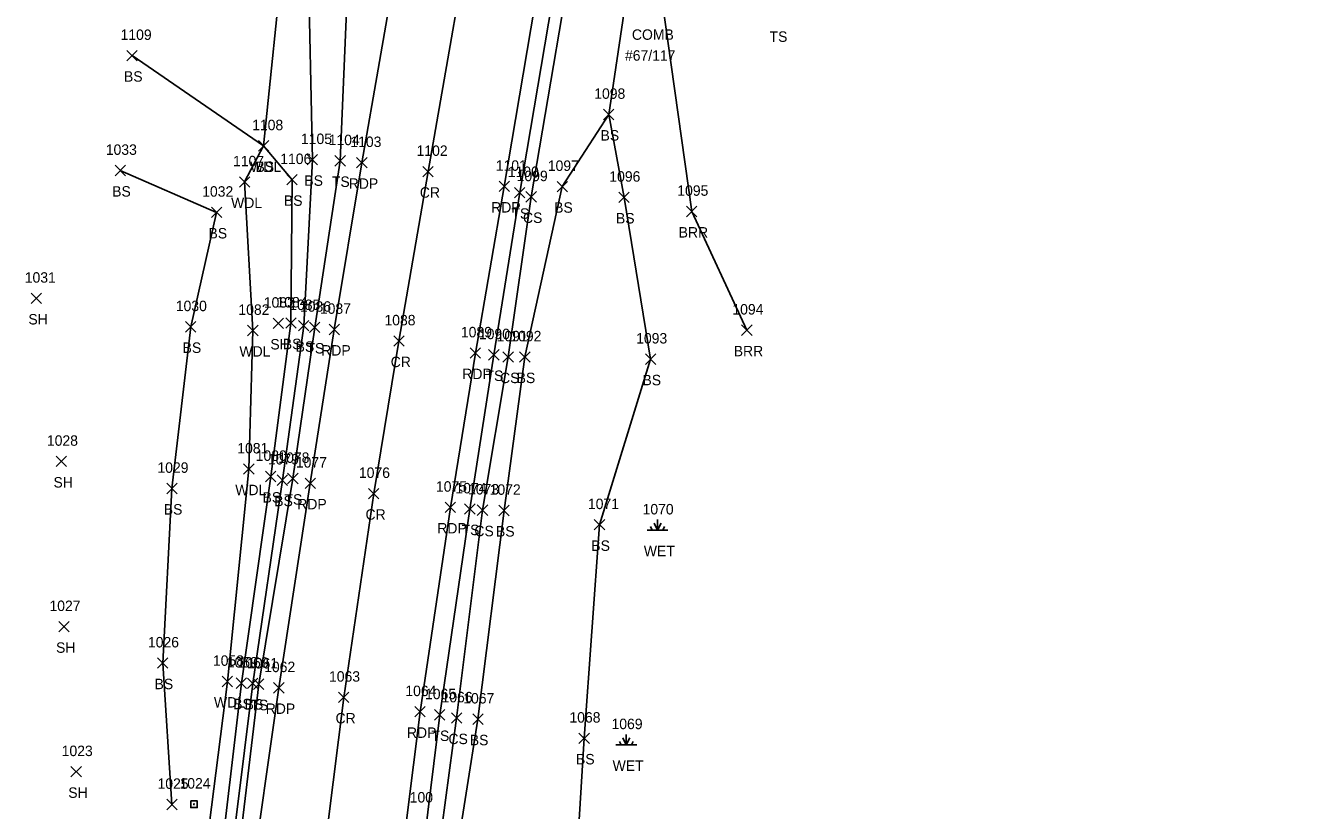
# Model space of a CAD drawing. Extents: x 1654425 to 1656893, y 667839 to 678429.
# Drawn here: x 1654466.9 to 1654714.2, y 667954.2 to 668104.4 of the extents above; entities that cross this region are included whole.
import ezdxf

# ---------------------------------------------------------------- set-up
doc = ezdxf.new("R2010")
doc.units = 0
for name, color, linetype in [('C_I', 7, 'Continuous'), ('L_A', 7, 'Continuous'), ('L_I', 7, 'Continuous'), ('L_TIC', 7, 'Continuous'), ('LABL', 7, 'Continuous'), ('LAWA', 7, 'Continuous'), ('LELB', 7, 'Continuous'), ('LWET', 7, 'Continuous'), ('P_A', 7, 'Continuous'), ('P_I', 7, 'Continuous'), ('P_TIC', 7, 'Continuous'), ('PET', 7, 'Continuous'), ('PRC', 7, 'Continuous'), ('S_I', 7, 'Continuous'), ('SRM', 7, 'Continuous'), ('U_A', 7, 'Continuous'), ('U_C', 7, 'Continuous')]:
    doc.layers.add(name, color=color, linetype=linetype)

msp = doc.modelspace()

# ---------------------------------------------------------------- linework, layer by layer
at = {"layer": 'L_TIC'}
for points in [[(1654486.26, 668097.75), (1654488.26, 668099.75)], [(1654488.26, 668097.75), (1654486.26, 668099.75)], [(1654577.54, 668086.47), (1654579.54, 668088.47)], [(1654579.54, 668086.47), (1654577.54, 668088.47)], [(1654577.54, 668086.47), (1654579.54, 668088.47)], [(1654579.54, 668086.47), (1654577.54, 668088.47)], [(1654511.45, 668080.46), (1654513.45, 668082.46)], [(1654513.45, 668080.46), (1654511.45, 668082.46)], [(1654511.45, 668080.46), (1654513.45, 668082.46)], [(1654513.45, 668080.46), (1654511.45, 668082.46)], [(1654520.8, 668077.81), (1654522.8, 668079.81)], [(1654522.8, 668077.81), (1654520.8, 668079.81)], [(1654526.11, 668077.6), (1654528.11, 668079.6)], [(1654528.11, 668077.6), (1654526.11, 668079.6)], [(1654484, 668075.74), (1654486, 668077.74)], [(1654486, 668075.74), (1654484, 668077.74)], [(1654507.8, 668073.55), (1654509.8, 668075.55)], [(1654509.8, 668073.55), (1654507.8, 668075.55)], [(1654516.89, 668073.98), (1654518.89, 668075.98)], [(1654518.89, 668073.98), (1654516.89, 668075.98)], [(1654568.65, 668072.66), (1654570.65, 668074.66)], [(1654570.65, 668072.66), (1654568.65, 668074.66)], [(1654560.5, 668071.5), (1654562.5, 668073.5)], [(1654562.5, 668071.5), (1654560.5, 668073.5)], [(1654562.69, 668070.7), (1654564.69, 668072.7)], [(1654564.69, 668070.7), (1654562.69, 668072.7)], [(1654580.49, 668070.6), (1654582.49, 668072.6)], [(1654582.49, 668070.6), (1654580.49, 668072.6)], [(1654502.45, 668067.73), (1654504.45, 668069.73)], [(1654504.45, 668067.73), (1654502.45, 668069.73)], [(1654593.45, 668067.9), (1654595.45, 668069.9)], [(1654595.45, 668067.9), (1654593.45, 668069.9)], [(1654467.9, 668051.26), (1654469.9, 668053.26)], [(1654469.9, 668051.26), (1654467.9, 668053.26)], [(1654497.49, 668045.81), (1654499.49, 668047.81)], [(1654499.49, 668045.81), (1654497.49, 668047.81)], [(1654509.39, 668045.1), (1654511.39, 668047.1)], [(1654511.39, 668045.1), (1654509.39, 668047.1)], [(1654514.25, 668046.47), (1654516.25, 668048.47)], [(1654516.25, 668046.47), (1654514.25, 668048.47)], [(1654516.68, 668046.52), (1654518.68, 668048.52)], [(1654518.68, 668046.52), (1654516.68, 668048.52)], [(1654519.13, 668046.02), (1654521.13, 668048.02)], [(1654521.13, 668046.02), (1654519.13, 668048.02)], [(1654521.23, 668045.7), (1654523.23, 668047.7)], [(1654523.23, 668045.7), (1654521.23, 668047.7)], [(1654604, 668045.16), (1654606, 668047.16)], [(1654606, 668045.16), (1654604, 668047.16)], [(1654555.54, 668040.44), (1654557.54, 668042.44)], [(1654557.54, 668040.44), (1654555.54, 668042.44)], [(1654558.28, 668040.03), (1654560.28, 668042.03)], [(1654560.28, 668040.03), (1654558.28, 668042.03)], [(1654561.47, 668040.03), (1654563.47, 668042.03)], [(1654563.47, 668040.03), (1654561.47, 668042.03)], [(1654585.57, 668039.61), (1654587.57, 668041.61)], [(1654587.57, 668039.61), (1654585.57, 668041.61)], [(1654472.72, 668020.03), (1654474.72, 668022.03)], [(1654474.72, 668020.03), (1654472.72, 668022.03)], [(1654508.61, 668018.56), (1654510.61, 668020.56)], [(1654510.61, 668018.56), (1654508.61, 668020.56)], [(1654512.8, 668017.14), (1654514.8, 668019.14)], [(1654514.8, 668017.14), (1654512.8, 668019.14)], [(1654515.04, 668016.45), (1654517.04, 668018.45)], [(1654517.04, 668016.45), (1654515.04, 668018.45)], [(1654517.04, 668016.75), (1654519.04, 668018.75)], [(1654519.04, 668016.75), (1654517.04, 668018.75)], [(1654493.89, 668014.85), (1654495.89, 668016.85)], [(1654495.89, 668014.85), (1654493.89, 668016.85)], [(1654550.95, 668010.91), (1654552.95, 668012.91)], [(1654552.95, 668010.91), (1654550.95, 668012.91)], [(1654553.38, 668010.7), (1654555.38, 668012.7)], [(1654555.38, 668010.7), (1654553.38, 668012.7)], [(1654557.51, 668010.64), (1654559.51, 668012.64)], [(1654559.51, 668010.64), (1654557.51, 668012.64)], [(1654575.77, 668007.9), (1654577.77, 668009.9)], [(1654577.77, 668007.9), (1654575.77, 668009.9)], [(1654473.2, 667988.38), (1654475.2, 667990.38)], [(1654475.2, 667988.38), (1654473.2, 667990.38)], [(1654492.12, 667981.41), (1654494.12, 667983.41)], [(1654494.12, 667981.41), (1654492.12, 667983.41)], [(1654504.51, 667977.89), (1654506.51, 667979.89)], [(1654506.51, 667977.89), (1654504.51, 667979.89)], [(1654507.18, 667977.57), (1654509.18, 667979.57)], [(1654509.18, 667977.57), (1654507.18, 667979.57)], [(1654509.36, 667977.52), (1654511.36, 667979.52)], [(1654511.36, 667977.52), (1654509.36, 667979.52)], [(1654510.52, 667977.38), (1654512.52, 667979.38)], [(1654512.52, 667977.38), (1654510.52, 667979.38)], [(1654545.18, 667971.49), (1654547.18, 667973.49)], [(1654547.18, 667971.49), (1654545.18, 667973.49)], [(1654548.41, 667970.89), (1654550.41, 667972.89)], [(1654550.41, 667970.89), (1654548.41, 667972.89)], [(1654552.5, 667970.67), (1654554.5, 667972.67)], [(1654554.5, 667970.67), (1654552.5, 667972.67)], [(1654572.84, 667967.01), (1654574.84, 667969.01)], [(1654574.84, 667967.01), (1654572.84, 667969.01)], [(1654475.54, 667960.6), (1654477.54, 667962.6)], [(1654477.54, 667960.6), (1654475.54, 667962.6)], [(1654493.9, 667954.33), (1654495.9, 667956.33)], [(1654495.9, 667954.33), (1654493.9, 667956.33)]]:
    msp.add_lwpolyline(points, dxfattribs=at)
at = {"layer": 'LABL'}
msp.add_lwpolyline([(1654605, 668046.16), (1654594.45, 668068.9), (1654587.86, 668115.59), (1654591.34, 668138.45), (1654594.61, 668153.33), (1654611.07, 668168.74), (1654623.05, 668204.29), (1654669.38, 668214.79), (1654714.24, 668210.79)], dxfattribs=at)
at = {"layer": 'LAWA'}
msp.add_lwpolyline([(1654487.86, 667850.24), (1654494.84, 667897.34), (1654500.67, 667940.77), (1654505.51, 667978.89), (1654509.61, 668019.56), (1654510.39, 668046.1), (1654508.8, 668074.55), (1654512.45, 668081.46), (1654516.35, 668119.35), (1654498.68, 668136.06), (1654489.89, 668151.28)], dxfattribs=at)
at = {"layer": 'LELB'}
for points in [[(1654495.43, 667849.08), (1654500.81, 667895.96), (1654505.52, 667939.5), (1654510.36, 667978.52), (1654516.04, 668017.45), (1654520.13, 668047.02), (1654521.8, 668078.81), (1654520.96, 668117.25), (1654511.8, 668137.4), (1654509.93, 668148.4), (1654514.52, 668176.02), (1654523.2, 668207.52), (1654535.05, 668244.08), (1654541.09, 668271.34), (1654546.04, 668295.57), (1654553.44, 668325.52), (1654559.28, 668346.56), (1654565.49, 668358.45)], [(1654497.51, 667848.84), (1654501.99, 667895.85), (1654506.8, 667938.86), (1654511.52, 667978.38), (1654518.04, 668017.75), (1654522.23, 668046.7), (1654527.11, 668078.6), (1654529.66, 668139.05), (1654535.37, 668180.01), (1654543.78, 668219.73), (1654556.62, 668268.25), (1654562.63, 668297.63), (1654565.24, 668311.03), (1654570.38, 668336.59), (1654576.33, 668345.51)], [(1654532.88, 667846.44), (1654536.81, 667893.31), (1654541.08, 667931.05), (1654546.18, 667972.49), (1654551.95, 668011.91), (1654556.54, 668041.44), (1654561.5, 668072.5), (1654571.11, 668129.18), (1654578.93, 668172.43), (1654586.94, 668211.68), (1654595.67, 668254.34), (1654607.41, 668286.92), (1654610.93, 668292.61), (1654617.54, 668318.12), (1654616.79, 668336.32)], [(1654543.76, 667929.96), (1654549.41, 667971.89), (1654554.38, 668011.7), (1654559.28, 668041.03), (1654563.69, 668071.7), (1654573.34, 668128.44), (1654581.87, 668172.56), (1654590.31, 668210.74), (1654599.29, 668252.88), (1654609.98, 668283.91), (1654610.93, 668292.61)], [(1654538.26, 667846.15), (1654542.65, 667893.12), (1654546.8, 667929.18), (1654553.5, 667971.67), (1654558.51, 668011.64), (1654562.47, 668041.03), (1654569.65, 668073.66), (1654578.54, 668087.47), (1654583.04, 668117.51)], [(1654492.62, 667849.25), (1654498.76, 667895.88), (1654503.7, 667940.07), (1654508.18, 667978.57), (1654513.8, 668018.14), (1654517.68, 668047.52), (1654517.89, 668074.98), (1654512.45, 668081.46), (1654487.26, 668098.75)], [(1654570.91, 667920.09), (1654573.84, 667968.01), (1654576.77, 668008.9), (1654586.57, 668040.61), (1654581.49, 668071.6), (1654578.54, 668087.47)], [(1654494.9, 667955.33), (1654493.12, 667982.41), (1654494.89, 668015.85), (1654498.49, 668046.81), (1654503.45, 668068.73), (1654485, 668076.74)]]:
    msp.add_lwpolyline(points, dxfattribs=at)
at = {"layer": 'LWET'}
for p, q in [((1654589.89, 668007.88), (1654585.89, 668007.88)), ((1654586.89, 668007.88), (1654586.56, 668008.55)), ((1654587.89, 668007.88), (1654587.22, 668009.21)), ((1654587.89, 668007.88), (1654587.89, 668009.88)), ((1654587.89, 668007.88), (1654588.56, 668009.21)), ((1654588.89, 668007.88), (1654589.22, 668008.55)), ((1654581.91, 667966.76), (1654581.24, 667968.09)), ((1654581.91, 667966.76), (1654581.91, 667968.76)), ((1654581.91, 667966.76), (1654582.58, 667968.09)), ((1654583.91, 667966.76), (1654579.91, 667966.76)), ((1654580.91, 667966.76), (1654580.58, 667967.42)), ((1654582.91, 667966.76), (1654583.24, 667967.42))]:
    msp.add_line(p, q, dxfattribs=at)
at = {"layer": 'P_TIC'}
for points in [[(1654530.26, 668077.24), (1654532.26, 668079.24)], [(1654532.26, 668077.24), (1654530.26, 668079.24)], [(1654542.94, 668075.54), (1654544.94, 668077.54)], [(1654544.94, 668075.54), (1654542.94, 668077.54)], [(1654557.55, 668072.69), (1654559.55, 668074.69)], [(1654559.55, 668072.69), (1654557.55, 668074.69)], [(1654524.99, 668045.3), (1654526.99, 668047.3)], [(1654526.99, 668045.3), (1654524.99, 668047.3)], [(1654537.36, 668043.09), (1654539.36, 668045.09)], [(1654539.36, 668043.09), (1654537.36, 668045.09)], [(1654552.01, 668040.79), (1654554.01, 668042.79)], [(1654554.01, 668040.79), (1654552.01, 668042.79)], [(1654520.39, 668015.85), (1654522.39, 668017.85)], [(1654522.39, 668015.85), (1654520.39, 668017.85)], [(1654532.53, 668013.87), (1654534.53, 668015.87)], [(1654534.53, 668013.87), (1654532.53, 668015.87)], [(1654547.22, 668011.23), (1654549.22, 668013.23)], [(1654549.22, 668011.23), (1654547.22, 668013.23)], [(1654514.37, 667976.68), (1654516.37, 667978.68)], [(1654516.37, 667976.68), (1654514.37, 667978.68)], [(1654526.79, 667974.85), (1654528.79, 667976.85)], [(1654528.79, 667974.85), (1654526.79, 667976.85)], [(1654541.41, 667972.09), (1654543.41, 667974.09)], [(1654543.41, 667972.09), (1654541.41, 667974.09)]]:
    msp.add_lwpolyline(points, dxfattribs=at)
at = {"layer": 'PET'}
for points in [[(1654500.93, 667848.14), (1654504.78, 667896.02), (1654509.67, 667937.82), (1654515.37, 667977.68), (1654521.39, 668016.85), (1654525.99, 668046.3), (1654531.26, 668078.24), (1654541.38, 668136.51), (1654548.54, 668178.15), (1654556.41, 668219.5), (1654564.06, 668264.06), (1654572.07, 668308.08), (1654579.91, 668345.23), (1654595.42, 668341.51), (1654611.88, 668337.75)], [(1654528.99, 667846.47), (1654531.96, 667893.38), (1654537.26, 667931.97), (1654542.41, 667973.09), (1654548.22, 668012.23), (1654553.01, 668041.79), (1654558.55, 668073.69), (1654568.05, 668129.99), (1654575.97, 668172.91), (1654583.21, 668212.31), (1654592.64, 668255.65), (1654604.22, 668302.74), (1654611.88, 668337.75)]]:
    msp.add_lwpolyline(points, dxfattribs=at)
at = {"layer": 'PRC'}
msp.add_lwpolyline([(1654514.39, 667847.42), (1654517.73, 667895.01), (1654522.68, 667935.26), (1654527.79, 667975.85), (1654533.53, 668014.87), (1654538.36, 668044.09), (1654543.94, 668076.54), (1654553.86, 668133.31), (1654561.61, 668175.74), (1654568.95, 668214.62), (1654577.86, 668259.83), (1654587.68, 668305.21), (1654595.42, 668341.51)], dxfattribs=at)
at = {"layer": 'SRM'}
msp.add_lwpolyline([(1654498.49, 667956), (1654499.74, 667956), (1654499.74, 667954.75), (1654498.49, 667954.75)], close=True, dxfattribs=at)
msp.add_circle((1654499.11, 667955.38), 0.0833, dxfattribs=at)

# ---------------------------------------------------------------- texts
at = {"layer": 'C_I'}
msp.add_text('100', height=2, dxfattribs=at).set_placement((1654540.43, 667955.71))
at = {"layer": 'L_A'}
for s, p in [('TS', (1654609.35, 668101.38)), ('BS', (1654485.7, 668093.75)), ('BS', (1654576.98, 668082.47)), ('BS', (1654576.98, 668082.47)), ('WDL', (1654509.87, 668076.46)), ('BS', (1654510.89, 668076.46)), ('BS', (1654520.25, 668073.81)), ('TS', (1654525.52, 668073.6)), ('BS', (1654483.44, 668071.74)), ('BS', (1654516.33, 668069.98)), ('WDL', (1654506.22, 668069.55)), ('TS', (1654559.91, 668067.5)), ('BS', (1654568.09, 668068.66)), ('CS', (1654562.13, 668066.7)), ('BS', (1654579.93, 668066.6)), ('BS', (1654501.89, 668063.73)), ('BRR', (1654591.94, 668063.9)), ('SH', (1654467.39, 668047.26)), ('BS', (1654496.93, 668041.81)), ('WDL', (1654507.81, 668041.1)), ('SH', (1654513.74, 668042.47)), ('BS', (1654516.12, 668042.52)), ('BS', (1654518.58, 668042.02)), ('TS', (1654520.64, 668041.7)), ('BRR', (1654602.49, 668041.16)), ('TS', (1654554.95, 668036.44)), ('CS', (1654557.73, 668036.03)), ('BS', (1654560.91, 668036.03)), ('BS', (1654585.01, 668035.61)), ('SH', (1654472.2, 668016.03)), ('WDL', (1654507.02, 668014.56)), ('BS', (1654512.24, 668013.14)), ('BS', (1654493.33, 668010.85)), ('BS', (1654514.48, 668012.45)), ('TS', (1654516.45, 668012.75)), ('TS', (1654550.36, 668006.91)), ('CS', (1654552.82, 668006.7)), ('BS', (1654556.95, 668006.64)), ('BS', (1654575.21, 668003.9)), ('WET', (1654585.27, 668002.88)), ('SH', (1654472.69, 667984.38)), ('BS', (1654491.56, 667977.41)), ('WDL', (1654502.93, 667973.89)), ('BS', (1654506.62, 667973.57)), ('BS', (1654508.8, 667973.52)), ('TS', (1654509.93, 667973.38)), ('TS', (1654544.59, 667967.49)), ('CS', (1654547.85, 667966.89)), ('BS', (1654551.94, 667966.67)), ('BS', (1654572.28, 667963.01)), ('WET', (1654579.29, 667961.76)), ('SH', (1654475.03, 667956.6))]:
    msp.add_text(s, height=2, dxfattribs=at).set_placement(p)
at = {"layer": 'L_I'}
for s, p in [('1109', (1654485.05, 668101.75)), ('1098', (1654575.77, 668090.47)), ('1098', (1654575.77, 668090.47)), ('1108', (1654510.25, 668084.46)), ('1108', (1654510.25, 668084.46)), ('1033', (1654482.22, 668079.74)), ('1105', (1654519.6, 668081.81)), ('1104', (1654524.91, 668081.6)), ('1107', (1654506.59, 668077.55)), ('1106', (1654515.63, 668077.98)), ('1100', (1654559.21, 668075.5)), ('1097', (1654566.88, 668076.66)), ('1099', (1654560.91, 668074.7)), ('1096', (1654578.66, 668074.6)), ('1032', (1654500.68, 668071.73)), ('1095', (1654591.68, 668071.9)), ('1031', (1654466.7, 668055.26)), ('1083', (1654512.48, 668050.47)), ('1084', (1654514.91, 668050.52)), ('1085', (1654517.36, 668050.02)), ('1030', (1654495.63, 668049.81)), ('1082', (1654507.62, 668049.1)), ('1086', (1654519.41, 668049.7)), ('1094', (1654602.23, 668049.16)), ('1090', (1654553.68, 668044.44)), ('1091', (1654557.08, 668044.03)), ('1092', (1654559.7, 668044.03)), ('1093', (1654583.8, 668043.61)), ('1028', (1654470.94, 668024.03)), ('1081', (1654507.4, 668022.56)), ('1080', (1654510.94, 668021.14)), ('1079', (1654513.26, 668020.45)), ('1078', (1654515.27, 668020.75)), ('1029', (1654492.11, 668018.85)), ('1074', (1654549.18, 668014.91)), ('1073', (1654551.61, 668014.7)), ('1072', (1654555.74, 668014.64)), ('1071', (1654574.56, 668011.9)), ('1070', (1654585.03, 668010.88)), ('1027', (1654471.43, 667992.38)), ('1026', (1654490.29, 667985.41)), ('1058', (1654502.74, 667981.89)), ('1059', (1654505.4, 667981.57)), ('1060', (1654507.45, 667981.52)), ('1061', (1654509.26, 667981.38)), ('1065', (1654543.36, 667975.49)), ('1066', (1654546.53, 667974.89)), ('1067', (1654550.68, 667974.67)), ('1068', (1654571.02, 667971.01)), ('1069', (1654579.08, 667969.76)), ('1023', (1654473.77, 667964.6)), ('1025', (1654492.13, 667958.33))]:
    msp.add_text(s, height=2, dxfattribs=at).set_placement(p)
at = {"layer": 'P_A'}
for s, p in [('RDP', (1654528.75, 668073.24)), ('CR', (1654542.37, 668071.54)), ('RDP', (1654556.03, 668068.69)), ('RDP', (1654523.48, 668041.3)), ('CR', (1654536.79, 668039.09)), ('RDP', (1654550.5, 668036.79)), ('RDP', (1654518.88, 668011.85)), ('CR', (1654531.96, 668009.87)), ('RDP', (1654545.71, 668007.23)), ('RDP', (1654512.85, 667972.68)), ('CR', (1654526.22, 667970.85)), ('RDP', (1654539.9, 667968.09))]:
    msp.add_text(s, height=2, dxfattribs=at).set_placement(p)
at = {"layer": 'P_I'}
for s, p in [('1103', (1654529.06, 668081.24)), ('1102', (1654541.74, 668079.54)), ('1101', (1654556.91, 668076.69)), ('1087', (1654523.22, 668049.3)), ('1088', (1654535.59, 668047.09)), ('1089', (1654550.23, 668044.79)), ('1077', (1654518.62, 668019.85)), ('1076', (1654530.7, 668017.87)), ('1075', (1654545.45, 668015.23)), ('1062', (1654512.55, 667980.68)), ('1063', (1654524.97, 667978.85)), ('1064', (1654539.59, 667976.09))]:
    msp.add_text(s, height=2, dxfattribs=at).set_placement(p)
at = {"layer": 'S_I'}
msp.add_text('1024', height=2, dxfattribs=at).set_placement((1654496.34, 667958.38))
at = {"layer": 'U_A'}
msp.add_text('COMB', height=2, dxfattribs=at).set_placement((1654582.99, 668101.77))
at = {"layer": 'U_C'}
msp.add_text('#67/117', height=2, dxfattribs=at).set_placement((1654581.66, 668097.77))

doc.saveas('drawing.dxf')
